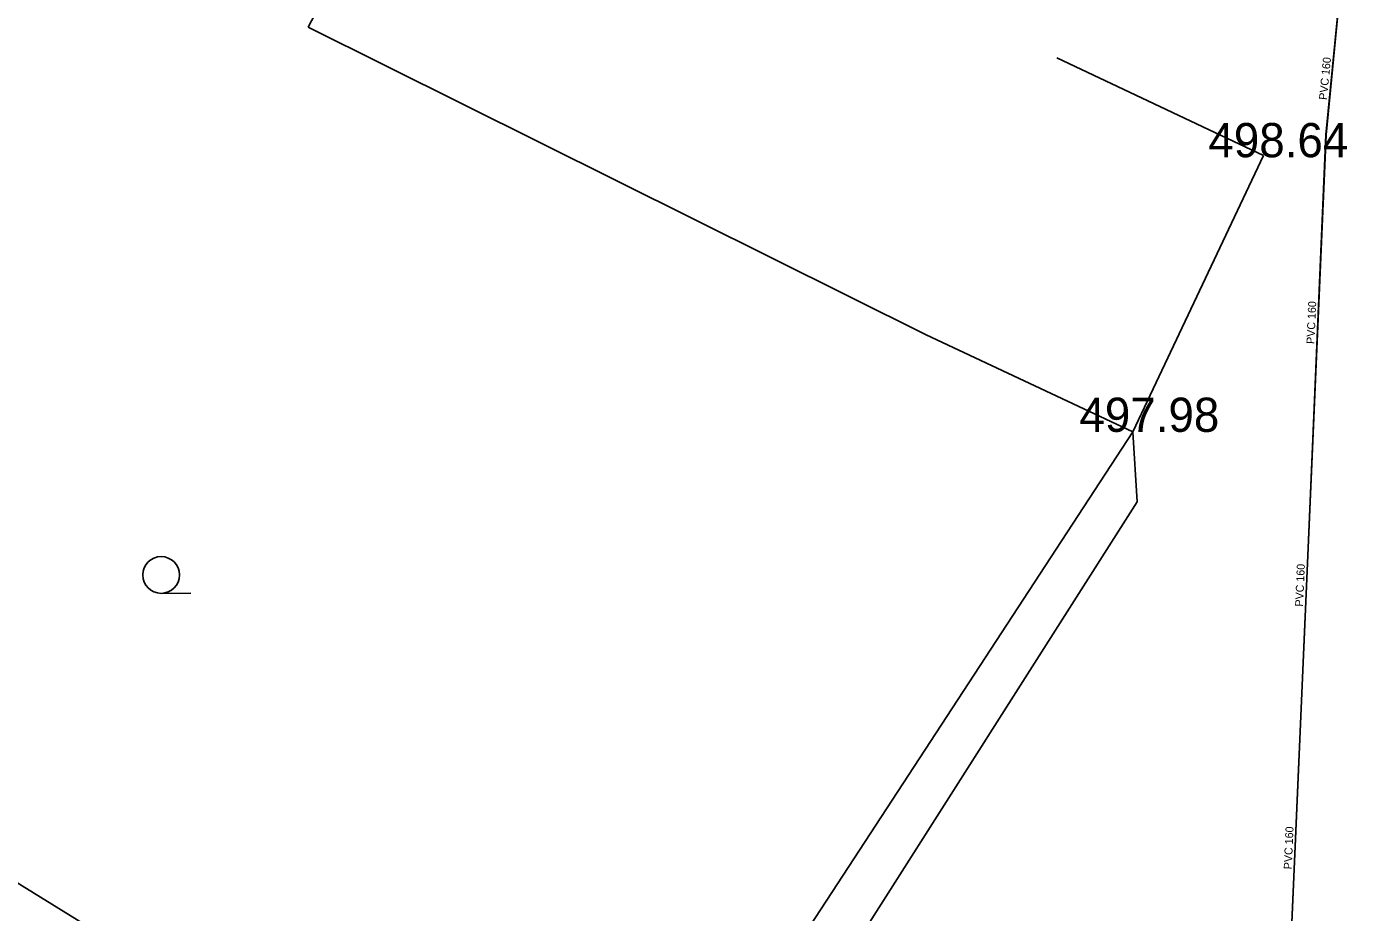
# Model space of a CAD drawing. Extents: x -668867 to -667827, y -1131943 to -1131019.
# Drawn here: x -668282.37 to -668253.04, y -1131620.92 to -1131601.51 of the extents above; entities that cross this region are included whole.
import ezdxf

# ---------------------------------------------------------------- set-up
doc = ezdxf.new("R2010")
doc.units = 0
for name, color, linetype in [('G_Bod_tecka', 7, 'Continuous'), ('G_Bod_vyska', 7, 'Continuous'), ('G_Budovy_Objekty', 7, 'Continuous'), ('G_Plochy_zpevnene', 7, 'Continuous'), ('G_Ploty', 7, 'Continuous'), ('G_Z_KANAL_podz_kotovane', 7, 'Continuous'), ('G_Zelen-Znacky', 7, 'Continuous'), ('Vrstva 13', 7, 'Continuous'), ('Vrstva 3', 7, 'Continuous')]:
    doc.layers.add(name, color=color, linetype=linetype)

msp = doc.modelspace()

# ---------------------------------------------------------------- linework, layer by layer
at = {"layer": 'G_Bod_tecka'}
for p, q in [((-668255.28, -1131604.37), (-668255.28, -1131604.37)), ((-668258.12, -1131610.39), (-668258.12, -1131610.39))]:
    msp.add_line(p, q, dxfattribs=at)
at = {"layer": 'G_Budovy_Objekty'}
for p, q in [((-668275.6, -1131600.39), (-668276.2, -1131601.52)), ((-668262.65, -1131608.26), (-668276.2, -1131601.52)), ((-668259.78, -1131602.19), (-668255.25, -1131604.33)), ((-668255.25, -1131604.33), (-668258.12, -1131610.39)), ((-668262.65, -1131608.26), (-668258.12, -1131610.39))]:
    msp.add_line(p, q, dxfattribs=at)
at = {"layer": 'G_Plochy_zpevnene'}
msp.add_lwpolyline([(-668247.03, -1131620.12), (-668247.64, -1131621.94), (-668248.11, -1131622.9), (-668248.79, -1131624.29), (-668252.99, -1131633.11), (-668253.29, -1131633.72), (-668264.61, -1131622.27), (-668258.02, -1131611.92), (-668258.12, -1131610.39)], dxfattribs=at)
at = {"layer": 'G_Ploty'}
for p, q in [((-668265.92, -1131622.32), (-668258.12, -1131610.39)), ((-668264.03, -1131631.7), (-668292.33, -1131614.27))]:
    msp.add_line(p, q, dxfattribs=at)
at = {"layer": 'G_Z_KANAL_podz_kotovane'}
msp.add_lwpolyline([(-668253.44, -1131599.35), (-668253.88, -1131603.88), (-668254.27, -1131612.93), (-668254.67, -1131621.99), (-668255.09, -1131624.77)], dxfattribs=at)
at = {"layer": 'G_Zelen-Znacky'}
msp.add_line((-668279.422, -1131613.93), (-668278.772, -1131613.927), dxfattribs=at)
msp.add_circle((-668279.422, -1131613.527), 0.403, dxfattribs=at)
at = {"layer": 'Vrstva 13'}
msp.add_lwpolyline([(-668253.438, -1131599.351), (-668253.883, -1131603.881), (-668254.275, -1131612.935), (-668254.666, -1131621.988), (-668255.087, -1131624.768)], dxfattribs=at)

# ---------------------------------------------------------------- texts
at = {"layer": 'G_Bod_vyska'}
for s, p in [('498.64', (-668256.46, -1131604.37)), ('497.98', (-668259.288, -1131610.39))]:
    msp.add_text(s, height=0.75, dxfattribs=at).set_placement(p)
at = {"layer": 'Vrstva 3'}
for rotation, p in [(84.3791, (-668253.862, -1131603.12)), (87.5156, (-668254.135, -1131608.467)), (87.5511, (-668254.384, -1131614.224)), (87.5171, (-668254.633, -1131619.982))]:
    msp.add_text('PVC 160', height=0.1755, rotation=rotation, dxfattribs=at).set_placement(p)

doc.saveas('drawing.dxf')
